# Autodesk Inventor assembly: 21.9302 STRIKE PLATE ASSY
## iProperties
Created: 2011-01
Part Number: 21.9302 STRIKE PLATE ASSY
Document SubType Name: Assembly
Designer: Administrator
Author: Administrator
